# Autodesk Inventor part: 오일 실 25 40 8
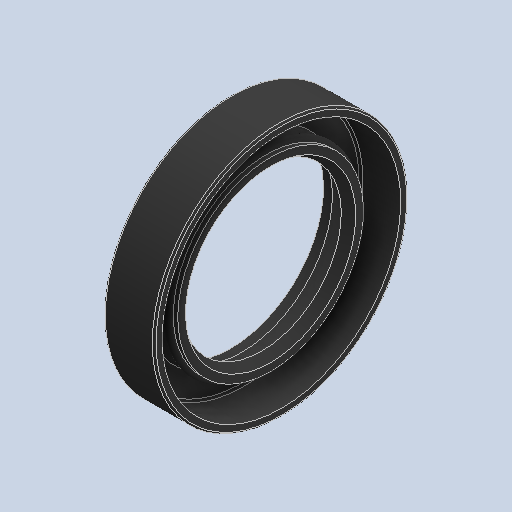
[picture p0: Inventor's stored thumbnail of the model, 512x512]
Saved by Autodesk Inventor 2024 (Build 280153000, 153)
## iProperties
Created: 2025-11
Part Number: 오일 실 25 40 8
Material: 고무
Description: 오일-실
Document SubType Name: Modeling
Designer: Eud07
Density: 0.93 g/cm^3
Appearance: 기본값
Author: jhkim
Sending System: Autodesk Inventor 2026
Preprocessor: ST-DEVELOPER v20.1
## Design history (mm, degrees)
node "오일 실 25 40 81"
node "솔리드1"
body "Solid1"
